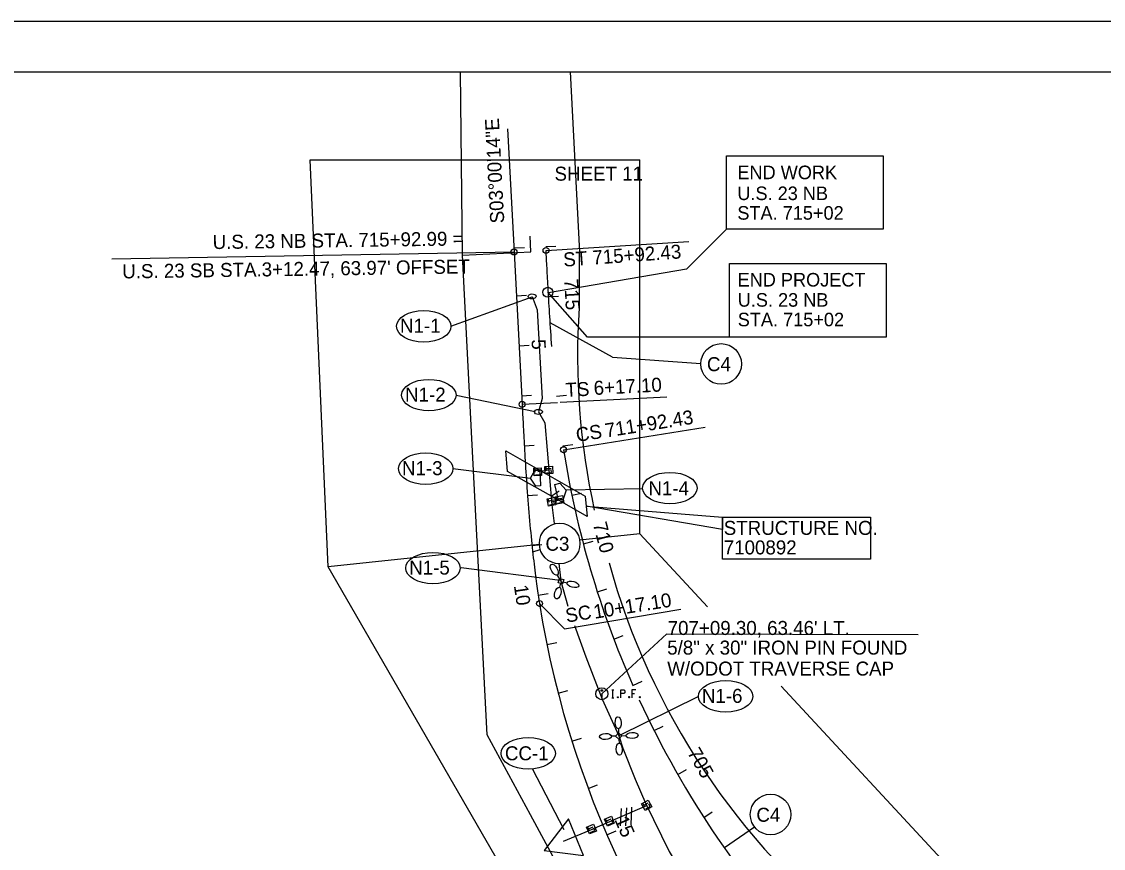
# Model space of a CAD drawing. Extents: x 310 to 1844719, y 48 to 494239.
# Drawn here: x 1835985 to 1838148, y 492586 to 494239 of the extents above; entities that cross this region are included whole.
import ezdxf

# ---------------------------------------------------------------- set-up
doc = ezdxf.new("R2010")
doc.units = 0
for name, color, linetype in [('BR_X_SV_Bottom_of_Beam_Text', 7, 'Continuous'), ('Clear Zones 30ft', 7, 'Continuous'), ('Default', 7, 'Continuous'), ('Guardrail', 7, 'Continuous'), ('LT_P_Control_Center', 7, 'Continuous'), ('LT_P_PullBox', 7, 'Continuous'), ('PV_X_Curb', 7, 'Continuous'), ('PV_X_EOP', 7, 'Continuous'), ('RW_X_CL_100_Stations', 7, 'Continuous'), ('RW_X_Esmt_LA', 7, 'Continuous'), ('SC_Scratch2', 7, 'Continuous'), ('Shoulder lines', 7, 'Continuous'), ('Traffic Sign', 7, 'Continuous'), ('UT_P_Electric_Cells', 7, 'Continuous'), ('VG_X_Tree_Line_Lt', 7, 'Continuous')]:
    doc.layers.add(name, color=color, linetype=linetype)

msp = doc.modelspace()

# ---------------------------------------------------------------- linework, layer by layer
at = {"layer": 'BR_X_SV_Bottom_of_Beam_Text'}
msp.add_line((1837145.1, 492896.3), (1837145.1, 492887.5), dxfattribs=at)
for points in [[(1837165.4, 492903.2), (1837168.9, 492903.2)], [(1837167.2, 492887.2), (1837167.2, 492903.2)], [(1837182.9, 492887.2), (1837182.8, 492903.2), (1837188.1, 492903.2), (1837188.7, 492903.1), (1837189.4, 492902.8), (1837189.8, 492902.6), (1837190.1, 492902.3), (1837190.5, 492901.7), (1837190.9, 492901.1), (1837191.1, 492900.1), (1837191.1, 492898.6), (1837191, 492898), (1837190.8, 492897.3), (1837190.3, 492896.4), (1837189.9, 492896), (1837189.6, 492895.8), (1837189, 492895.5), (1837188.1, 492895.4), (1837182.8, 492895.4)], [(1837212.9, 492903.2), (1837205.3, 492903.2), (1837205.3, 492887.2)], [(1837165.4, 492887.2), (1837169, 492887.2)], [(1837176.8, 492889.3), (1837177.3, 492889.3), (1837177.7, 492889.1), (1837178, 492888.6), (1837178, 492888), (1837177.7, 492887.5), (1837177.3, 492887.2), (1837176.8, 492887.2), (1837176.5, 492887.4), (1837176.1, 492888), (1837176.1, 492888.6), (1837176.5, 492889.1), (1837176.8, 492889.3)], [(1837199.3, 492889.4), (1837199.8, 492889.4), (1837200.2, 492889.1), (1837200.5, 492888.6), (1837200.5, 492888), (1837200.2, 492887.5), (1837199.8, 492887.2), (1837199.3, 492887.2), (1837198.9, 492887.5), (1837198.6, 492888), (1837198.6, 492888.6), (1837198.9, 492889.1), (1837199.3, 492889.4)], [(1837205.3, 492895.4), (1837210.7, 492895.4)], [(1837220.8, 492889.4), (1837221.3, 492889.4), (1837221.6, 492889.1), (1837222, 492888.6), (1837222, 492888), (1837221.7, 492887.5), (1837221.3, 492887.3), (1837220.8, 492887.3), (1837220.4, 492887.5), (1837220.1, 492888), (1837220.1, 492888.6), (1837220.4, 492889.1), (1837220.8, 492889.4)]]:
    msp.add_lwpolyline(points, dxfattribs=at)
for centre, radius in [((1837145.1, 492895.2), 12), ((1837145.1, 492901.7), 1.6)]:
    msp.add_circle(centre, radius, dxfattribs=at)
at = {"layer": 'Clear Zones 30ft'}
msp.add_lwpolyline([(1833749.7, 494138.7), (1840149.7, 494138.7), (1840149.7, 489938.7), (1833749.7, 489938.7)], close=True, dxfattribs=at)
at = {"layer": 'Default'}
for p, q in [((1836956.8, 494024.2), (1836969.7, 493778)), ((1836598, 493149.1), (1836562.1, 493962.5)), ((1836562.1, 493962.5), (1837221.2, 493962.5)), ((1837221.2, 493214.6), (1837221.2, 493962.5)), ((1836969.7, 493778), (1836985.7, 493473.8)), ((1836956.7, 493339.6), (1836952.9, 493381)), ((1836952.9, 493381), (1837055.5, 493322.3)), ((1837065.6, 493277.8), (1836956.7, 493339.6)), ((1837055.5, 493322.3), (1837112, 493290.2)), ((1837112, 493290.2), (1837115.8, 493249.4)), ((1837115.8, 493249.4), (1837065.6, 493277.8)), ((1837221.2, 493214.6), (1837100.9, 493202)), ((1837356.1, 493069.2), (1837221.2, 493214.6)), ((1837020.2, 493193.5), (1836598, 493149.1)), ((1836983.7, 492481.4), (1836598, 493149.1)), ((1837060.2, 493125.7), (1837066.6, 493114.7)), ((1838105.1, 492261.8), (1837503.3, 492910.5))]:
    msp.add_line(p, q, dxfattribs=at)
for centre, start, end in [((1838954.8, 493681.9), 189.0038, 203.7765), ((1838906.9, 493374.4), 189.0038, 224.841), ((1838954.8, 493681.9), 204.7226, 223.7988)]:
    msp.add_arc(centre, 1909.9, start, end, dxfattribs=at)
for points in [[(1837045.2, 493589.3), (1837043.7, 493608.9), (1837040.8, 493650.7), (1837037.8, 493703.7), (1837035.4, 493748), (1837034.2, 493770.2), (1837033.6, 493781.3)], [(1836985.7, 493473.8), (1836986.2, 493462.7), (1836987.4, 493440.5), (1836989.8, 493396.1), (1836993, 493340.6), (1836997.7, 493274.1), (1837003.5, 493207.7), (1837009.6, 493152.5), (1837015.5, 493108.4), (1837018.8, 493086.5), (1837020.5, 493075.5)]]:
    msp.add_open_spline(points, degree=3, dxfattribs=at)
at = {"layer": 'LT_P_Control_Center'}
for p, q in [((1837060.2, 493125.7), (1837056.1, 493132.7)), ((1837062.3, 493115.9), (1837060.2, 493108)), ((1837067.8, 493119.1), (1837075.6, 493117)), ((1837178.3, 492825.3), (1837178.7, 492817.2)), ((1837185.3, 492811.1), (1837193.4, 492811.4)), ((1837172.6, 492810.6), (1837164.5, 492810.2)), ((1837179.2, 492804.5), (1837179.5, 492796.4))]:
    msp.add_line(p, q, dxfattribs=at)
for points in [[(1837021.2, 493343.1), (1837022.7, 493310.8), (1837013, 493310.3), (1837002.5, 493326), (1837011.5, 493342.7)], [(1837058.4, 493282), (1837051.3, 493313.6), (1837060.8, 493315.8), (1837073.8, 493302.1), (1837067.9, 493284.2)], [(1837057.9, 493117), (1837060.2, 493125.7), (1837068.9, 493123.4), (1837066.6, 493114.7)], [(1837179.2, 492804.5), (1837172.6, 492810.6), (1837178.7, 492817.2), (1837185.3, 492811.1)]]:
    msp.add_lwpolyline(points, close=True, dxfattribs=at)
for centre, major_axis, ratio in [((1837005.6, 493689.5), (-8, -0.26), 0.625), ((1837018.3, 493458.6), (-8, -0.26), 0.625), ((1837050.1, 493143.1), (-6.1, 10.4), 0.5), ((1837087.3, 493113.9), (-11.7, 3.1), 0.5), ((1837057.1, 493096.4), (3.1, 11.7), 0.5), ((1837177.8, 492837.3), (-0.5, 12), 0.5), ((1837152.4, 492809.7), (-12, -0.5), 0.5), ((1837205.4, 492811.9), (12, 0.5), 0.5), ((1837180, 492784.3), (-0.5, 12.1), 0.5)]:
    msp.add_ellipse(centre, major_axis=major_axis, ratio=ratio, dxfattribs=at)
at = {"layer": 'LT_P_PullBox'}
for p, q in [((1837039.1, 493342.4), (1837017.2, 493338.5)), ((1837043.8, 493290.4), (1837059.8, 493300.5)), ((1837044.5, 493279), (1837060.6, 493282.6)), ((1837178.9, 492810.8), (1837187, 492786.1)), ((1837187, 492786.1), (1837211.7, 492724.3)), ((1837211.7, 492724.3), (1837232.9, 492674.8)), ((1837125.7, 492624.2), (1837236.6, 492672.4)), ((1837232.9, 492674.8), (1837280, 492580)), ((1837126.8, 492624.7), (1837067.5, 492599.6))]:
    msp.add_line(p, q, dxfattribs=at)
for points in [[(1837005.6, 493689.4), (1837015.8, 493662.9), (1837025.5, 493485.5)], [(1837025.5, 493485.5), (1837018.3, 493458.8), (1837031.1, 493436.8), (1837045, 493273), (1837049.5, 493235.7)], [(1837059.1, 493155.8), (1837063.4, 493120), (1837077.2, 493070.4)], [(1837090.5, 493031.9), (1837113.1, 492969.2), (1837145.8, 492884.3), (1837178.9, 492810.8), (1837187, 492786.1), (1837211.7, 492724.3), (1837232.9, 492674.8), (1837280, 492580), (1837320.6, 492511.8), (1837370.9, 492433.7)]]:
    msp.add_lwpolyline(points, dxfattribs=at)
at = {"layer": 'PV_X_Curb'}
for p, q in [((1836866.3, 493771.8), (1836862.7, 494138.7)), ((1837082, 494138.7), (1837100.7, 493777.6)), ((1837003.2, 493778.8), (1837001.5, 493810.2)), ((1836866.3, 493771.8), (1837003.2, 493778.8)), ((1836885.3, 493405.5), (1836866.3, 493771.8)), ((1837100.3, 493661.9), (1837100.7, 493777.6)), ((1836916, 492813), (1836885.3, 493405.5)), ((1837002.7, 492653), (1836916, 492813)), ((1837276.3, 492148), (1837002.7, 492653))]:
    msp.add_line(p, q, dxfattribs=at)
for centre, start, end in [((1838544.9, 493572.1), 176.2688, 192.3534), ((1838555, 493544.4), 195.5242, 231.7004)]:
    msp.add_arc(centre, 1448.4, start, end, dxfattribs=at)
at = {"layer": 'PV_X_EOP'}
for p, q in [((1836990.2, 493786.7), (1836970.2, 493785.6)), ((1837033.1, 493788.9), (1837053, 493790.1)), ((1836974.3, 493690.6), (1836994.3, 493691.6)), ((1837038.6, 493689), (1837058.6, 493690.2)), ((1836979.5, 493590.7), (1836999.5, 493591.8)), ((1836984.8, 493490.8), (1837004.7, 493491.9)), ((1837054.4, 493489.8), (1837074.3, 493491.9)), ((1836990.1, 493391), (1837010.1, 493392.1)), ((1837067.3, 493390.5), (1837087.1, 493393.6)), ((1836996.5, 493291.3), (1837016.5, 493292.8)), ((1837085.2, 493292.1), (1837104.7, 493296.2)), ((1837005.4, 493191.6), (1837025.3, 493193.7)), ((1837108.1, 493194.8), (1837127.5, 493199.9)), ((1837017.9, 493092.4), (1837037.7, 493095.3)), ((1837136.1, 493098.8), (1837155.2, 493105)), ((1837169.1, 493004.5), (1837187.8, 493011.6)), ((1837035.3, 492993.9), (1837054.9, 492997.9)), ((1837207.1, 492911.9), (1837225.4, 492920)), ((1837057.8, 492896.5), (1837077.1, 492901.5)), ((1837249.7, 492821.5), (1837267.6, 492830.5)), ((1837085.3, 492800.4), (1837104.4, 492806.4)), ((1837297.1, 492733.5), (1837314.5, 492743.4)), ((1837117.8, 492705.8), (1837136.6, 492712.8)), ((1837349, 492648), (1837365.8, 492658.8)), ((1837155.3, 492613.1), (1837173.6, 492621.1))]:
    msp.add_line(p, q, dxfattribs=at)
at = {"layer": 'RW_X_CL_100_Stations'}
for p, q in [((1837033.6, 493781.3), (1837318.9, 493799)), ((1836969.7, 493778.1), (1836165.7, 493764.1))]:
    msp.add_line(p, q, dxfattribs=at)
at = {"layer": 'RW_X_Esmt_LA'}
msp.add_lwpolyline([(1833449.7, 489838.7), (1840249.7, 489838.7), (1840249.7, 494238.7), (1833449.7, 494238.7)], close=True, dxfattribs=at)
at = {"layer": 'SC_Scratch2'}
msp.add_lwpolyline([(1837108.7, 492572.1), (1837078.7, 492644.9), (1837029.6, 492582.1)], close=True, dxfattribs=at)
at = {"layer": 'Shoulder lines'}
for p, q in [((1837314.2, 493744.2), (1837394.4, 493823.6)), ((1837314.3, 493744.2), (1837038.2, 493696.5)), ((1837116.2, 493608.2), (1837037.1, 493697.7)), ((1836843.5, 493630), (1837006, 493688.8)), ((1837400.6, 493608.2), (1837116.2, 493608.2)), ((1836853.6, 493492.1), (1837011.8, 493459.2)), ((1836847.3, 493345.1), (1837002.5, 493326)), ((1837226.8, 493305.1), (1837073.8, 493302.1)), ((1836863.6, 493147.3), (1837061.5, 493122.5)), ((1837145.1, 492895.2), (1837274.7, 493015.2)), ((1837274.3, 493015.2), (1837777.5, 493013.8)), ((1837338.2, 492889.9), (1837178.9, 492810.8)), ((1837005.6, 492745.8), (1837069.4, 492624)), ((1837183.6, 492665.8), (1837181.7, 492630.8)), ((1837194.1, 492667.2), (1837192.6, 492630.8)), ((1837204.3, 492668.2), (1837202.8, 492633.3))]:
    msp.add_line(p, q, dxfattribs=at)
for points in [[(1837394.4, 493970.8), (1837707.5, 493970.8), (1837707.5, 493823.6), (1837394.4, 493823.6)], [(1837400.6, 493755.4), (1837713.7, 493755.4), (1837713.7, 493608.2), (1837400.6, 493608.2)]]:
    msp.add_lwpolyline(points, close=True, dxfattribs=at)
msp.add_circle((1837037.1, 493697.7), 10, dxfattribs=at)
for centre in [(1836789.1, 493629.7), (1836799.2, 493492.1), (1836793, 493345.1), (1837281.1, 493306.2), (1836807.4, 493146.3), (1837392.6, 492889.9), (1836997.9, 492776)]:
    msp.add_ellipse(centre, major_axis=(-54.4, 0), ratio=0.57803, dxfattribs=at)
at = {"layer": 'Traffic Sign'}
for p, q in [((1837166.4, 493567.8), (1837041.6, 493636.6)), ((1837343, 493554.5), (1837166.5, 493567.6)), ((1837062, 493477.8), (1837275.1, 493489)), ((1836985.7, 493473.8), (1837056.7, 493477.5)), ((1837068.5, 493383), (1837351.5, 493427.9)), ((1837006.8, 493178.7), (1837022, 493183.4)), ((1837450.5, 492628.7), (1837390.2, 492586.8))]:
    msp.add_line(p, q, dxfattribs=at)
msp.add_lwpolyline([(1837020.5, 493075.5), (1837070.7, 493024.9), (1837303.1, 493064.5)], dxfattribs=at)
for centre, radius in [((1836969.4, 493778.3), 6), ((1837033.6, 493781.3), 6), ((1837383.6, 493554.4), 40.6), ((1836985.7, 493473.8), 6), ((1837068.5, 493383), 6), ((1837060.8, 493195.4), 40.6), ((1837020.5, 493075.5), 6), ((1837482.5, 492653.7), 40.6)]:
    msp.add_circle(centre, radius, dxfattribs=at)
at = {"layer": 'UT_P_Electric_Cells'}
for p, q in [((1837016.9, 493338.8), (1837016.9, 493338.8)), ((1837039.1, 493342.4), (1837039.1, 493342.4)), ((1837044.5, 493279), (1837044.5, 493279)), ((1837060.6, 493282.6), (1837060.6, 493282.6)), ((1837234.7, 492672.1), (1837234.7, 492672.1)), ((1837160.2, 492640.3), (1837160.2, 492640.3)), ((1837124.3, 492624.7), (1837124.3, 492624.7))]:
    msp.add_line(p, q, dxfattribs=at)
for points in [[(1837009.7, 493331), (1837009.1, 493346), (1837024.1, 493346.6), (1837024.7, 493331.6)], [(1837031.9, 493334.6), (1837031.3, 493349.6), (1837046.3, 493350.2), (1837046.9, 493335.3)], [(1837038.4, 493270.3), (1837035.8, 493285.1), (1837050.6, 493287.7), (1837053.2, 493272.9)], [(1837054.5, 493273.9), (1837051.9, 493288.7), (1837066.7, 493291.3), (1837069.3, 493276.5)], [(1837231.5, 492662), (1837224.7, 492675.3), (1837238, 492682.1), (1837244.8, 492668.8)], [(1837156.2, 492630.4), (1837150.4, 492644.2), (1837164.2, 492650.1), (1837170, 492636.3)], [(1837120.3, 492614.8), (1837114.4, 492628.6), (1837128.3, 492634.5), (1837134.1, 492620.7)]]:
    msp.add_lwpolyline(points, close=True, dxfattribs=at)
for points in [[(1837011.9, 493338.3), (1837011.7, 493344.6)], [(1837011.8, 493341.5), (1837021.8, 493341.9)], [(1837012.2, 493333.1), (1837022.1, 493333.6), (1837021.9, 493339)], [(1837034.1, 493342), (1837033.8, 493348.2)], [(1837034, 493345.1), (1837044, 493345.6)], [(1837034.3, 493336.8), (1837044.3, 493337.2), (1837044.1, 493342.6)], [(1837055.7, 493281.5), (1837054.6, 493287.6)], [(1837039.6, 493277.9), (1837038.5, 493284)], [(1837039.1, 493281), (1837048.9, 493282.7)], [(1837040.5, 493272.8), (1837050.3, 493274.5), (1837049.4, 493279.9)], [(1837055.2, 493284.6), (1837065, 493286.3)], [(1837056.6, 493276.4), (1837066.4, 493278.1), (1837065.5, 493283.4)], [(1837230.4, 492669.6), (1837227.6, 492675.1)], [(1837229, 492672.4), (1837237.9, 492676.9)], [(1837232.8, 492664.9), (1837241.7, 492669.5), (1837239.2, 492674.3)], [(1837155.7, 492638.1), (1837153.3, 492643.8)], [(1837154.5, 492641), (1837163.7, 492644.9)], [(1837157.7, 492633.3), (1837166.9, 492637.2), (1837164.8, 492642.2)], [(1837119.8, 492622.5), (1837117.3, 492628.2)], [(1837118.5, 492625.4), (1837127.7, 492629.3)], [(1837121.8, 492617.7), (1837131, 492621.6), (1837128.9, 492626.6)]]:
    msp.add_lwpolyline(points, dxfattribs=at)
at = {"layer": 'VG_X_Tree_Line_Lt'}
for p, q in [((1837113.9, 493269.8), (1837386.3, 493247.9)), ((1837386.3, 493223.2), (1837113.9, 493269.8)), ((1837386.3, 493247.9), (1837386.3, 493223.2))]:
    msp.add_line(p, q, dxfattribs=at)
msp.add_lwpolyline([(1837386.3, 493247.9), (1837682, 493247.9), (1837682, 493164.5), (1837386.3, 493164.5)], close=True, dxfattribs=at)

# ---------------------------------------------------------------- texts
at = {"layer": 'Default'}
for s, p in [('SHEET 11', (1837050.5, 493920.8)), ('STRUCTURE NO.', (1837388.8, 493212.7)), ('7100892', (1837388.8, 493173.7))]:
    msp.add_text(s, height=28, dxfattribs=at).set_placement(p)
at = {"layer": 'Guardrail'}
msp.add_text('S03°00\'14"E', height=28, rotation=93.0038, dxfattribs=at).set_placement((1836950.2, 493836.2))
at = {"layer": 'PV_X_EOP'}
for s, rotation, p in [('715', 273.3241, (1837069.7, 493723.7)), ('5', 273.0038, (1837004.4, 493603.2)), ('710', 284.7765, (1837126.9, 493234.4)), ('10', 278.5018, (1836969.1, 493111.1)), ("707+09.30, 63.46' LT.", 0.0079, (1837276.7, 493012.6)), ('5/8" x 30" IRON PIN FOUND ', 0.0079, (1837275.8, 492973.4)), ('W/ODOT TRAVERSE CAP', 0.0079, (1837275.8, 492931.4)), ('705', 299.7765, (1837315.2, 492777.5)), ('15', 293.4908, (1837169.8, 492643.5))]:
    msp.add_text(s, height=28, rotation=rotation, dxfattribs=at).set_placement(p)
at = {"layer": 'RW_X_CL_100_Stations'}
for s, rotation, p in [('U.S. 23 NB STA. 715+92.99 = ', 0.831, (1836367.2, 493784)), ('ST 715+92.43', 4.0721, (1837069, 493748.8)), ("U.S. 23 SB STA.3+12.47, 63.97' OFFSET", 0.831, (1836186.4, 493725.3))]:
    msp.add_text(s, height=28, rotation=rotation, dxfattribs=at).set_placement(p)
at = {"layer": 'Shoulder lines'}
for s, height, p in [('END WORK', 27.1, (1837416.1, 493923.8)), ('U.S. 23 NB', 27.1, (1837416, 493882)), ('STA. 715+02', 27.104, (1837416, 493842.8)), ('END PROJECT', 27.104, (1837416.5, 493709.2)), ('U.S. 23 NB', 27.1, (1837416.8, 493668.9)), ('STA. 715+02', 27.104, (1837416.8, 493629.7)), ('N1-1', 28, (1836741.6, 493616.8)), ('N1-2', 28, (1836751.7, 493479.1)), ('N1-3', 28, (1836745.5, 493332.1)), ('N1-4', 28, (1837238.2, 493292.1)), ('N1-5', 28, (1836759.9, 493133.3)), ('N1-6', 28, (1837345.1, 492876.9)), ('CC-1', 28, (1836951.3, 492762.1))]:
    msp.add_text(s, height=height, dxfattribs=at).set_placement(p)
at = {"layer": 'Traffic Sign'}
for s, p in [('C4', (1837355.2, 493540)), ('C3', (1837032.4, 493181)), ('C4', (1837454.1, 492639.2))]:
    msp.add_text(s, height=28, dxfattribs=at).set_placement(p)
for s, rotation, p in [('6+17.10', 3.0038, (1837129.4, 493492.3)), ('TS', 3.0038, (1837073.1, 493488.4)), ('711+92.43', 9.0038, (1837153.8, 493407.3)), ('CS', 9.0038, (1837095.6, 493398.4)), ('10+17.10', 9.0038, (1837130.7, 493044.9)), ('SC', 9.0038, (1837074.7, 493037.3))]:
    msp.add_text(s, height=28, rotation=rotation, dxfattribs=at).set_placement(p)

doc.saveas('drawing.dxf')
